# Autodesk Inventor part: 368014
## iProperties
Created: 2006-08
Part Number: 368014
Material: 8 vz
Description: Sechskantmutter
Vendor: Autodesk Inc.
Document SubType Name: Modeling
Standard: DIN 934
Designer: I.Baliuc
Standards Organization: DIN
Language: de-DE
Size Designation: M12
Categories: <MemberInstance Version="R10.0.0"><Categories><Category DisplayName="Schrauben" InternalName="e4da775c-781d-43d5-af7c-5136215cf5a6" Mnemonic="FSTN"><Category Di
Density: 7.86 g/cm^3
Mass: 17.5637 g
Surface Area: 13.3413 cm^2
Volume: 2.23456 cm^3
Abmessung: M12
Author: T.Messerschmitt
Comments: DIN 934 - M12
Revision Number: 368014
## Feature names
1. Körper [Extrusion]
2. Fase1 [Revolution]
3. Gewinde [Hole]
4. Fase2 [Chamfer]
5. Fase3 [Chamfer]
